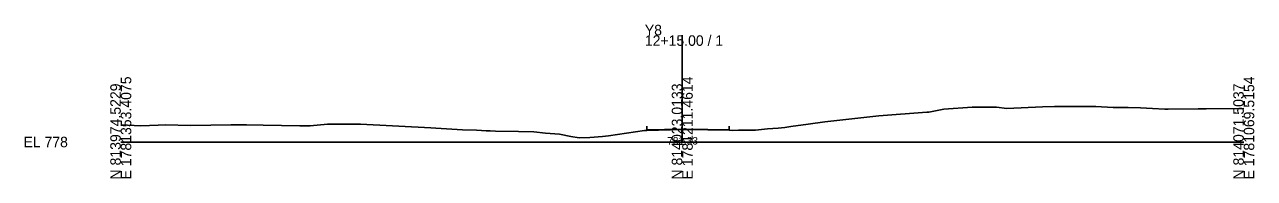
# Model space of a CAD drawing. Extents: x -26 to 303, y -10 to 5036.
# Drawn here: x -25.7 to 302.8, y 3990.3 to 4031.3 of the extents above; entities that cross this region are included whole.
import ezdxf

# ---------------------------------------------------------------- set-up
doc = ezdxf.new("R2010")
doc.units = 0
for name, color, linetype in [('Exist Cross Section Cell', 7, 'Continuous'), ('Exist XS Center Line Elevation Label', 7, 'Continuous'), ('Exist XS Ground Line', 7, 'Continuous'), ('Prop XS EOT Tick Mark', 7, 'Continuous'), ('Prop XS Finish Grade Pavement', 7, 'Continuous')]:
    doc.layers.add(name, color=color, linetype=linetype)

msp = doc.modelspace()

# ---------------------------------------------------------------- linework, layer by layer
at = {"layer": 'Exist Cross Section Cell'}
for p, q in [((150, 4000), (150, 4028.45)), ((0, 4000), (150, 4000)), ((150, 4000), (300, 4000))]:
    msp.add_line(p, q, dxfattribs=at)
at = {"layer": 'Exist XS Ground Line'}
for p, q in [((215.86, 4007.95), (219.91, 4008.73)), ((219.91, 4008.73), (227.45, 4009.29)), ((227.45, 4009.29), (231.52, 4009.3)), ((231.52, 4009.3), (233.9, 4009.31)), ((233.9, 4009.31), (236.69, 4008.91)), ((236.69, 4008.91), (246.21, 4009.39)), ((246.21, 4009.39), (249.4, 4009.48)), ((249.4, 4009.48), (255.24, 4009.45)), ((255.24, 4009.45), (259.06, 4009.46)), ((259.06, 4009.46), (260.44, 4009.43)), ((260.44, 4009.43), (265.15, 4009.24)), ((265.15, 4009.24), (267.66, 4009.21)), ((267.66, 4009.21), (269.11, 4009.18)), ((269.11, 4009.18), (272.42, 4009.13)), ((272.42, 4009.13), (275.61, 4008.93)), ((275.61, 4008.93), (278.94, 4008.78)), ((278.94, 4008.78), (279.78, 4008.75)), ((279.78, 4008.75), (287.85, 4008.82)), ((287.85, 4008.82), (288.74, 4008.81)), ((288.74, 4008.81), (289.92, 4008.82)), ((289.92, 4008.82), (300, 4008.91)), ((183.61, 4004.73), (188.08, 4005.39)), ((188.08, 4005.39), (198.53, 4006.53)), ((198.53, 4006.53), (202.51, 4006.94)), ((202.51, 4006.94), (215.35, 4007.92)), ((215.35, 4007.92), (215.86, 4007.95)), ((0, 4004.62), (5.33, 4004.34)), ((5.33, 4004.34), (9.99, 4004.53)), ((9.99, 4004.53), (11.88, 4004.61)), ((11.88, 4004.61), (18.7, 4004.42)), ((18.7, 4004.42), (29.37, 4004.58)), ((29.37, 4004.58), (33.63, 4004.54)), ((33.63, 4004.54), (38.08, 4004.53)), ((38.08, 4004.53), (47.84, 4004.34)), ((47.84, 4004.34), (50.56, 4004.29)), ((50.56, 4004.29), (55.25, 4004.76)), ((55.25, 4004.76), (64.02, 4004.73)), ((64.02, 4004.73), (82.81, 4003.81)), ((82.81, 4003.81), (84.2, 4003.71)), ((84.2, 4003.71), (91.26, 4003.29)), ((91.26, 4003.29), (95.04, 4003.17)), ((95.04, 4003.17), (96.37, 4003.11)), ((96.37, 4003.11), (97.62, 4003.01)), ((97.62, 4003.01), (98.67, 4002.97)), ((98.67, 4002.97), (100.07, 4002.93)), ((100.07, 4002.93), (106.22, 4002.82)), ((106.22, 4002.82), (110.35, 4002.69)), ((110.35, 4002.69), (113.43, 4002.4)), ((113.43, 4002.4), (117.24, 4002.11)), ((117.24, 4002.11), (120.27, 4001.45)), ((128.69, 4001.5), (130.28, 4001.67)), ((130.28, 4001.67), (139.93, 4003.03)), ((139.93, 4003.03), (140.49, 4003.1)), ((140.49, 4003.1), (150, 4003.33)), ((150, 4003.33), (150.57, 4003.34)), ((150.57, 4003.34), (151.1, 4003.33)), ((151.1, 4003.33), (162.54, 4003.12)), ((162.54, 4003.12), (163.36, 4003.07)), ((163.36, 4003.07), (165, 4003.12)), ((165, 4003.12), (169.6, 4003.19)), ((169.6, 4003.19), (171.19, 4003.35)), ((171.19, 4003.35), (172.78, 4003.53)), ((172.78, 4003.53), (175.61, 4003.67)), ((175.61, 4003.67), (177.42, 4003.91)), ((177.42, 4003.91), (179, 4004.12)), ((179, 4004.12), (183.61, 4004.73)), ((120.27, 4001.45), (122.49, 4001.12)), ((122.49, 4001.12), (125.28, 4001.21)), ((125.28, 4001.21), (128.69, 4001.5))]:
    msp.add_line(p, q, dxfattribs=at)
at = {"layer": 'Prop XS EOT Tick Mark'}
for p, q in [((140.49, 4003.23), (140.49, 4004.23)), ((162.54, 4003.25), (162.54, 4004.25))]:
    msp.add_line(p, q, dxfattribs=at)
at = {"layer": 'Prop XS Finish Grade Pavement'}
for p, q in [((140.49, 4003.23), (150, 4003.46)), ((150, 4003.46), (150.57, 4003.47)), ((150.57, 4003.47), (151.1, 4003.46)), ((151.1, 4003.46), (162.54, 4003.25))]:
    msp.add_line(p, q, dxfattribs=at)

# ---------------------------------------------------------------- texts
at = {"layer": 'Exist Cross Section Cell'}
for s, p in [('Y8', (140, 4028.45)), ('12+15.00 / 1', (140, 4025.65)), ('EL 778', (-26, 3998.6))]:
    msp.add_text(s, height=2.8, dxfattribs=at).set_placement(p)
for s, p in [('N 813974.5229', (0, 3990)), ('E 1781353.4075', (2.8, 3990)), ('N 814023.0133', (150, 3990)), ('E 1781211.4614', (152.8, 3990)), ('N 814071.5037', (300, 3990)), ('E 1781069.5154', (302.8, 3990))]:
    msp.add_text(s, height=2.8, rotation=90, dxfattribs=at).set_placement(p)
at = {"layer": 'Exist XS Center Line Elevation Label'}
msp.add_text('781.33', height=2, dxfattribs=at).set_placement((145.99, 3999.33))

doc.saveas('drawing.dxf')
